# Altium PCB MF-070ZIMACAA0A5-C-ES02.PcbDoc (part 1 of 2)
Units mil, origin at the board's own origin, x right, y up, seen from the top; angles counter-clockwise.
Board outline 4023.75 x 4574.93 mil, 4 copper layers (TopLayer, LAYER2:GND, LAYER3:PW, BottomLayer); 140 components, 66 nets, 413 pads, 523 vias.
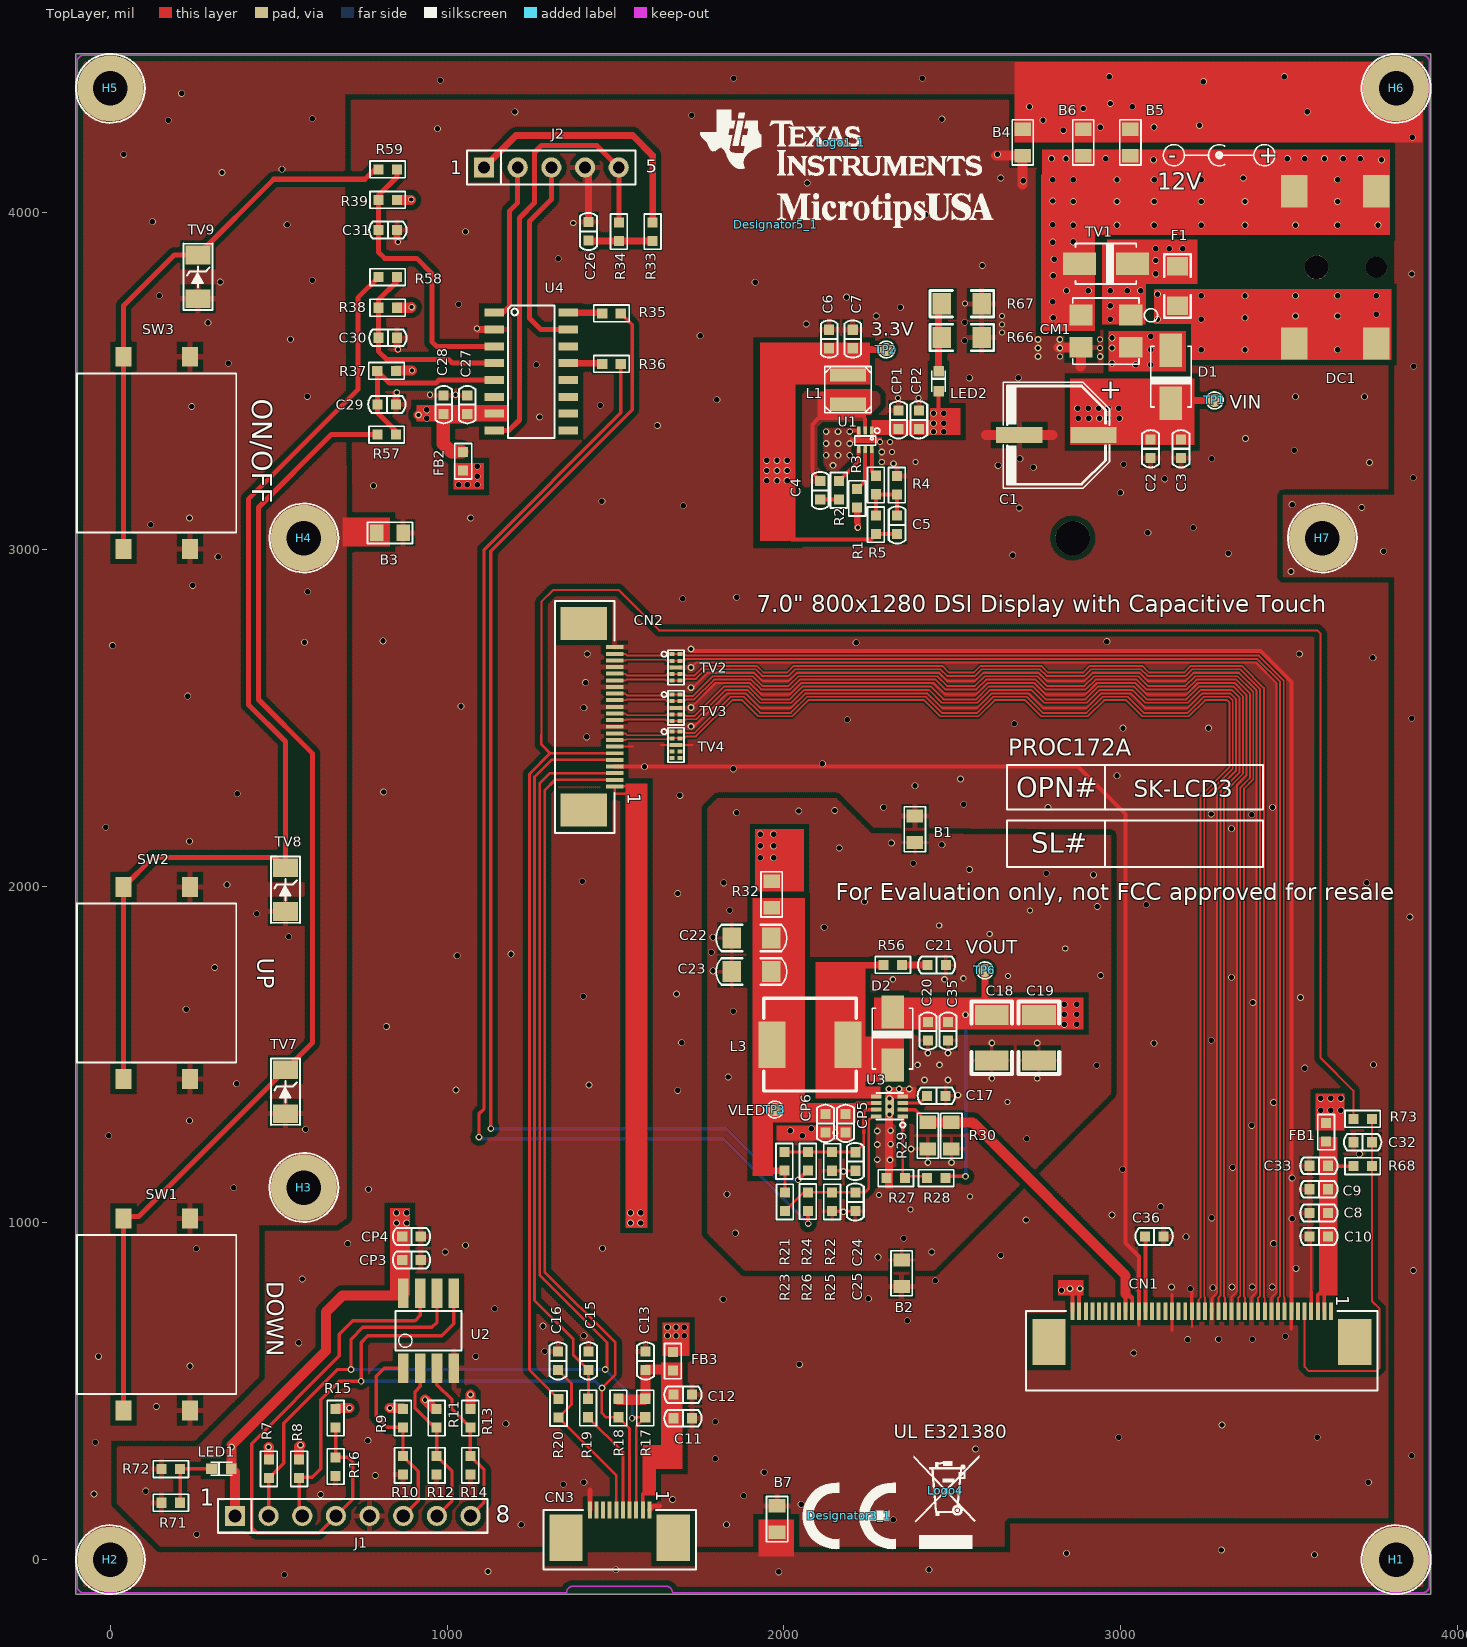
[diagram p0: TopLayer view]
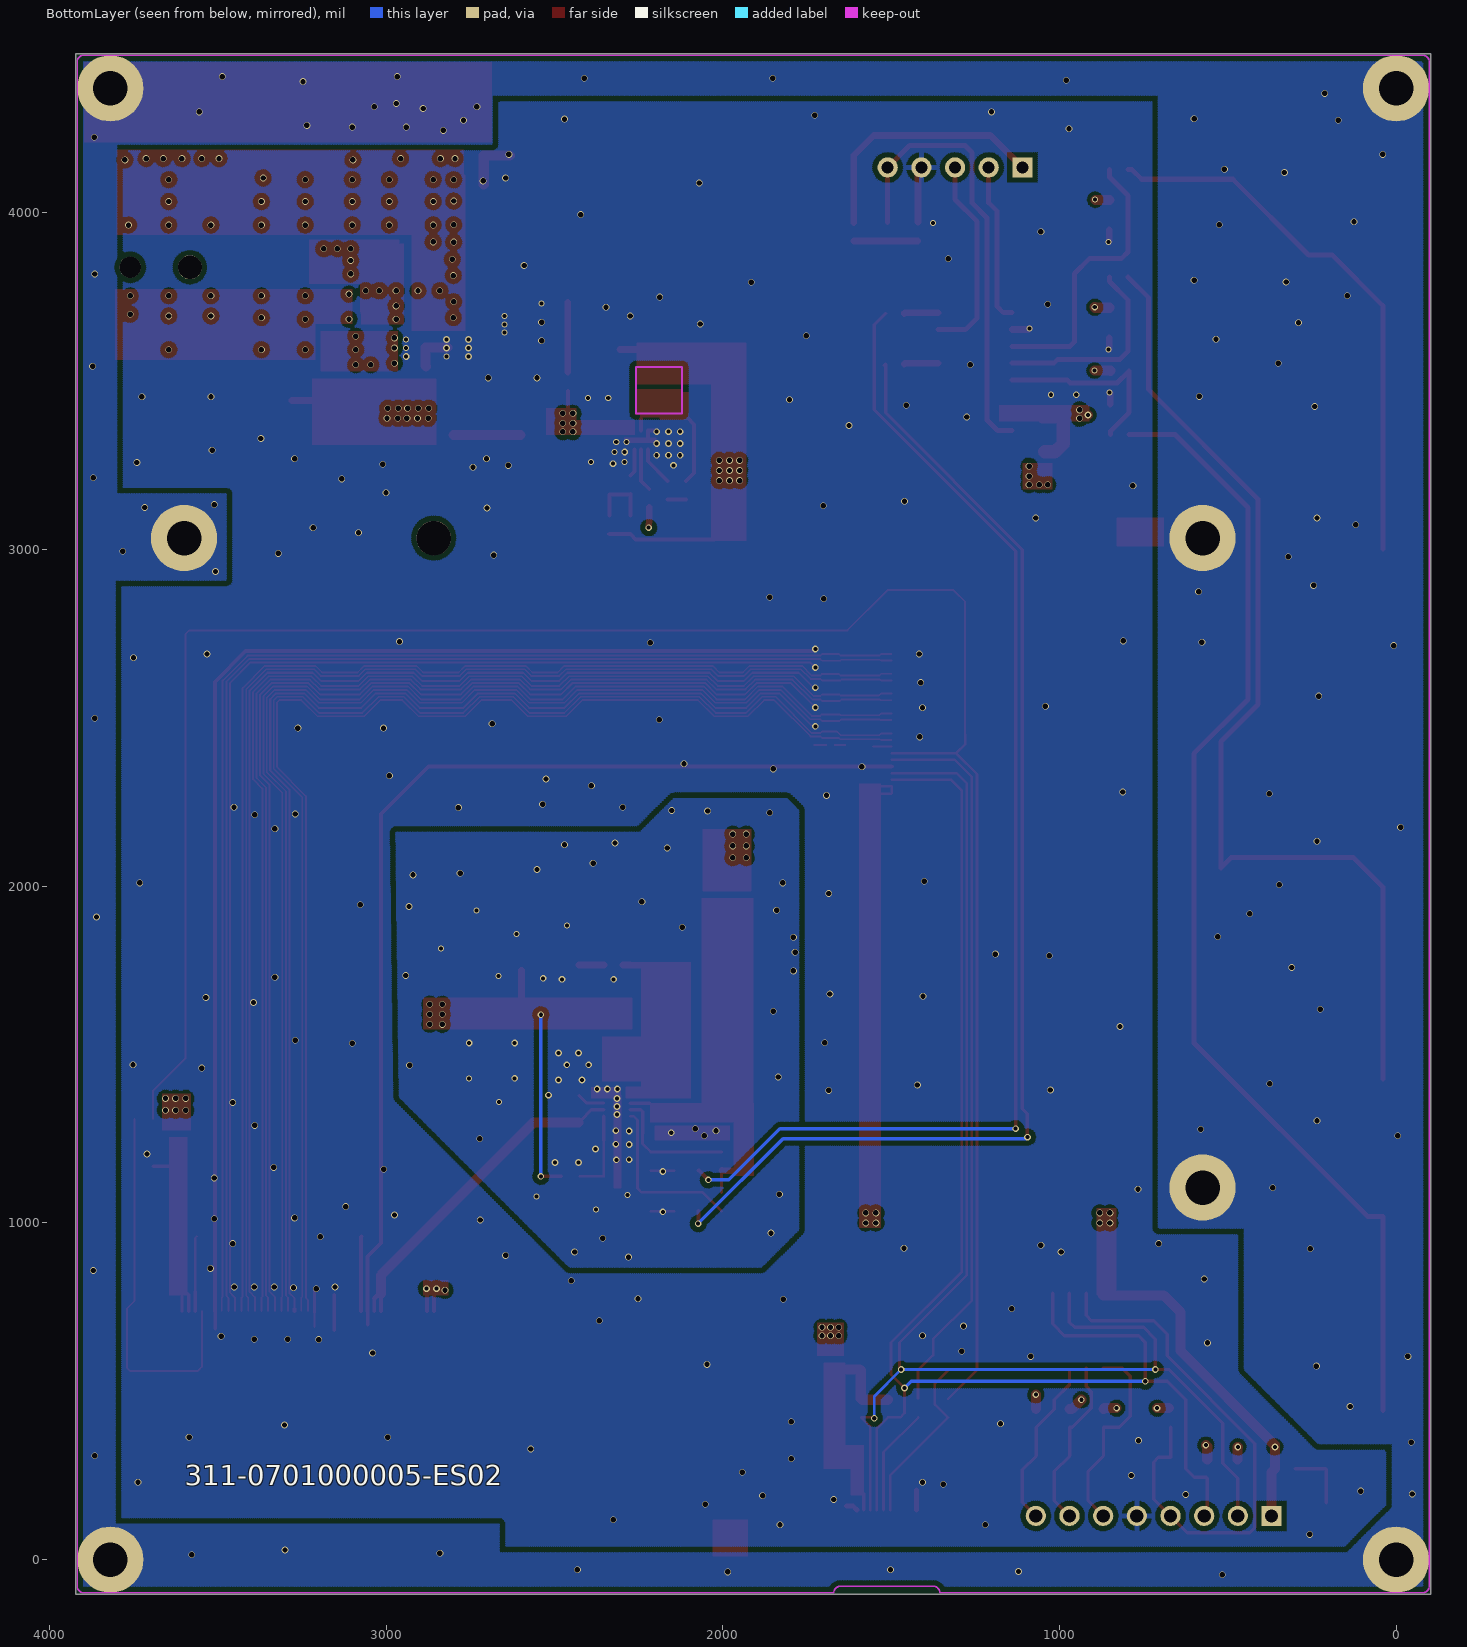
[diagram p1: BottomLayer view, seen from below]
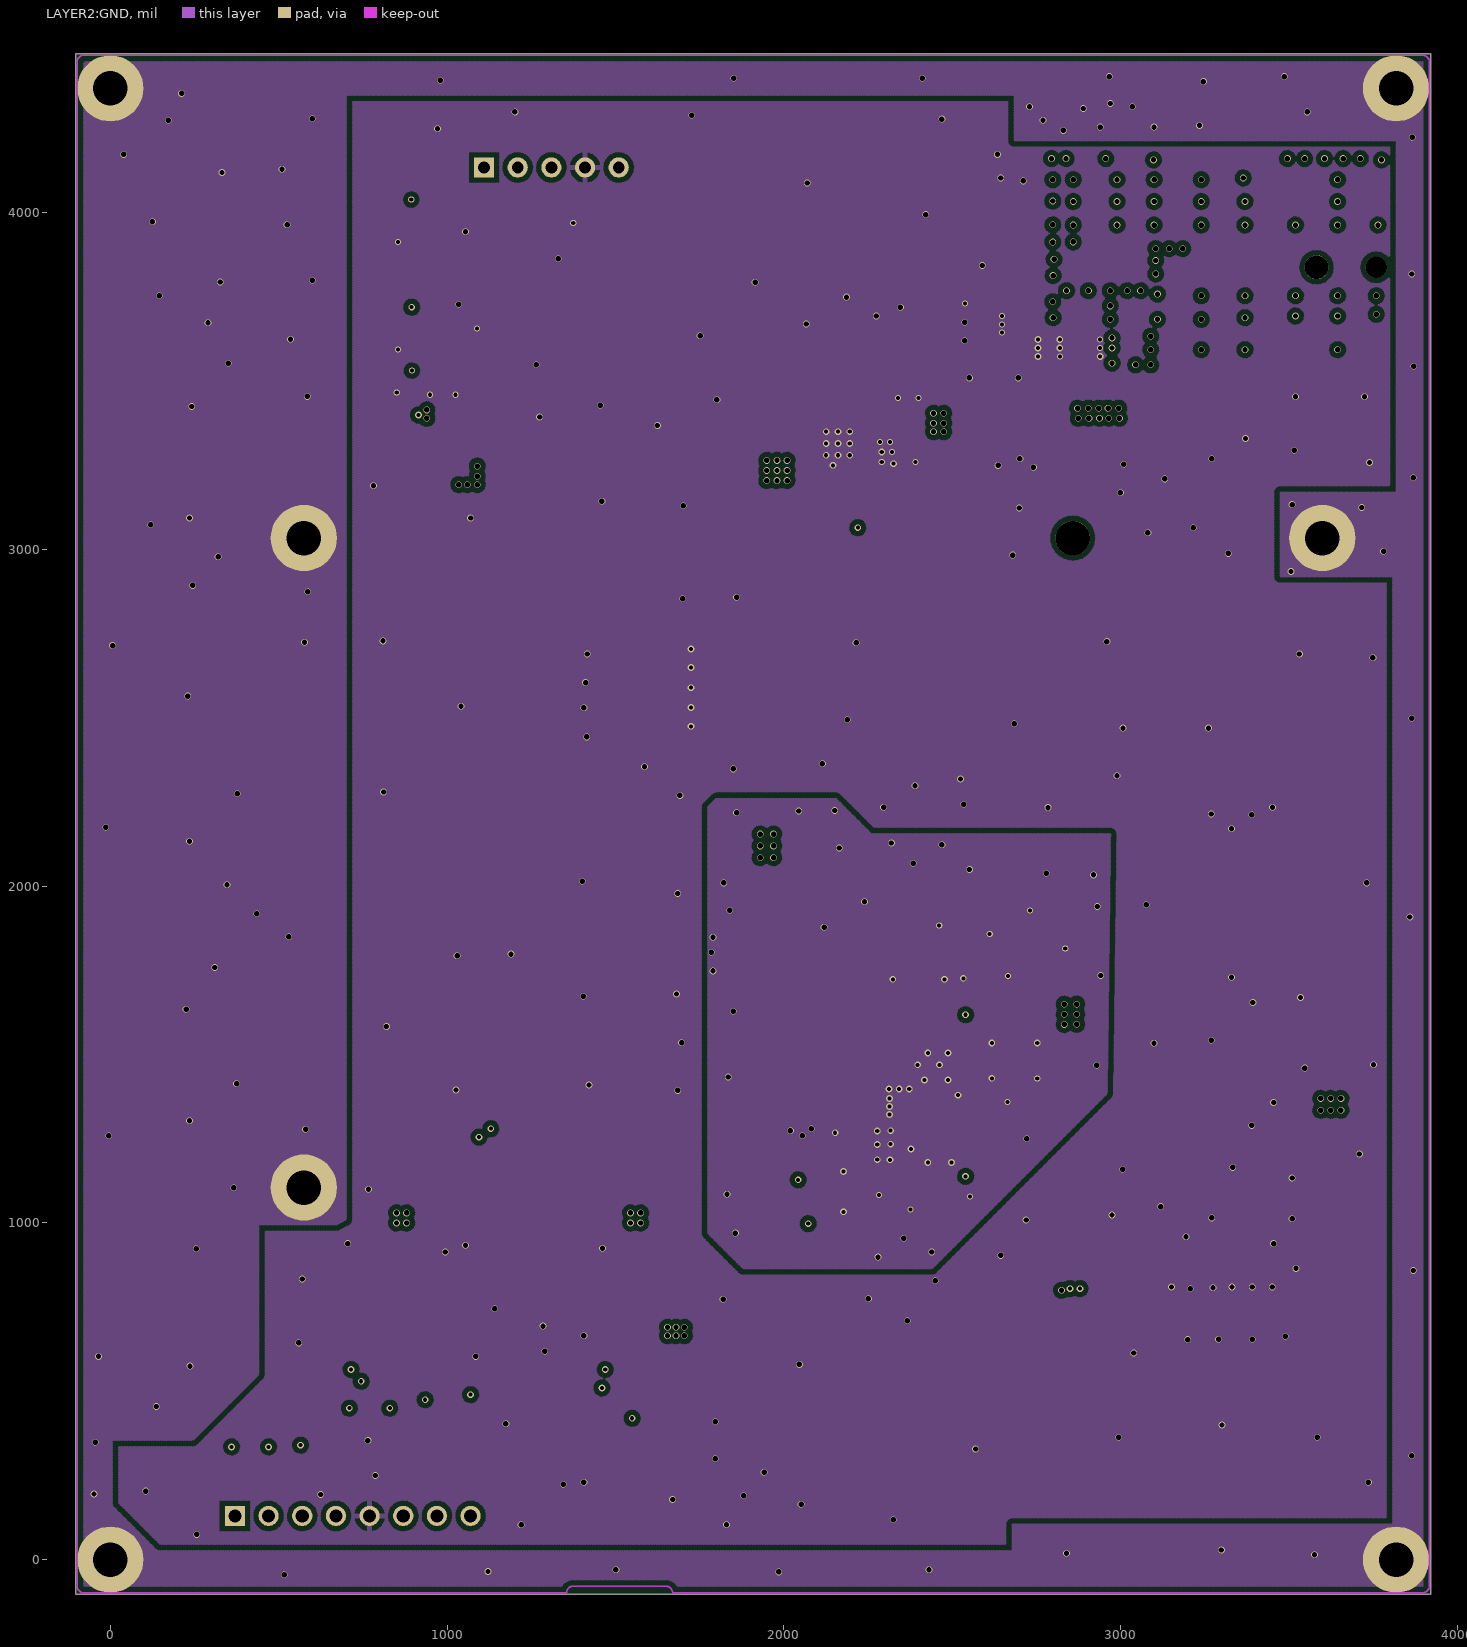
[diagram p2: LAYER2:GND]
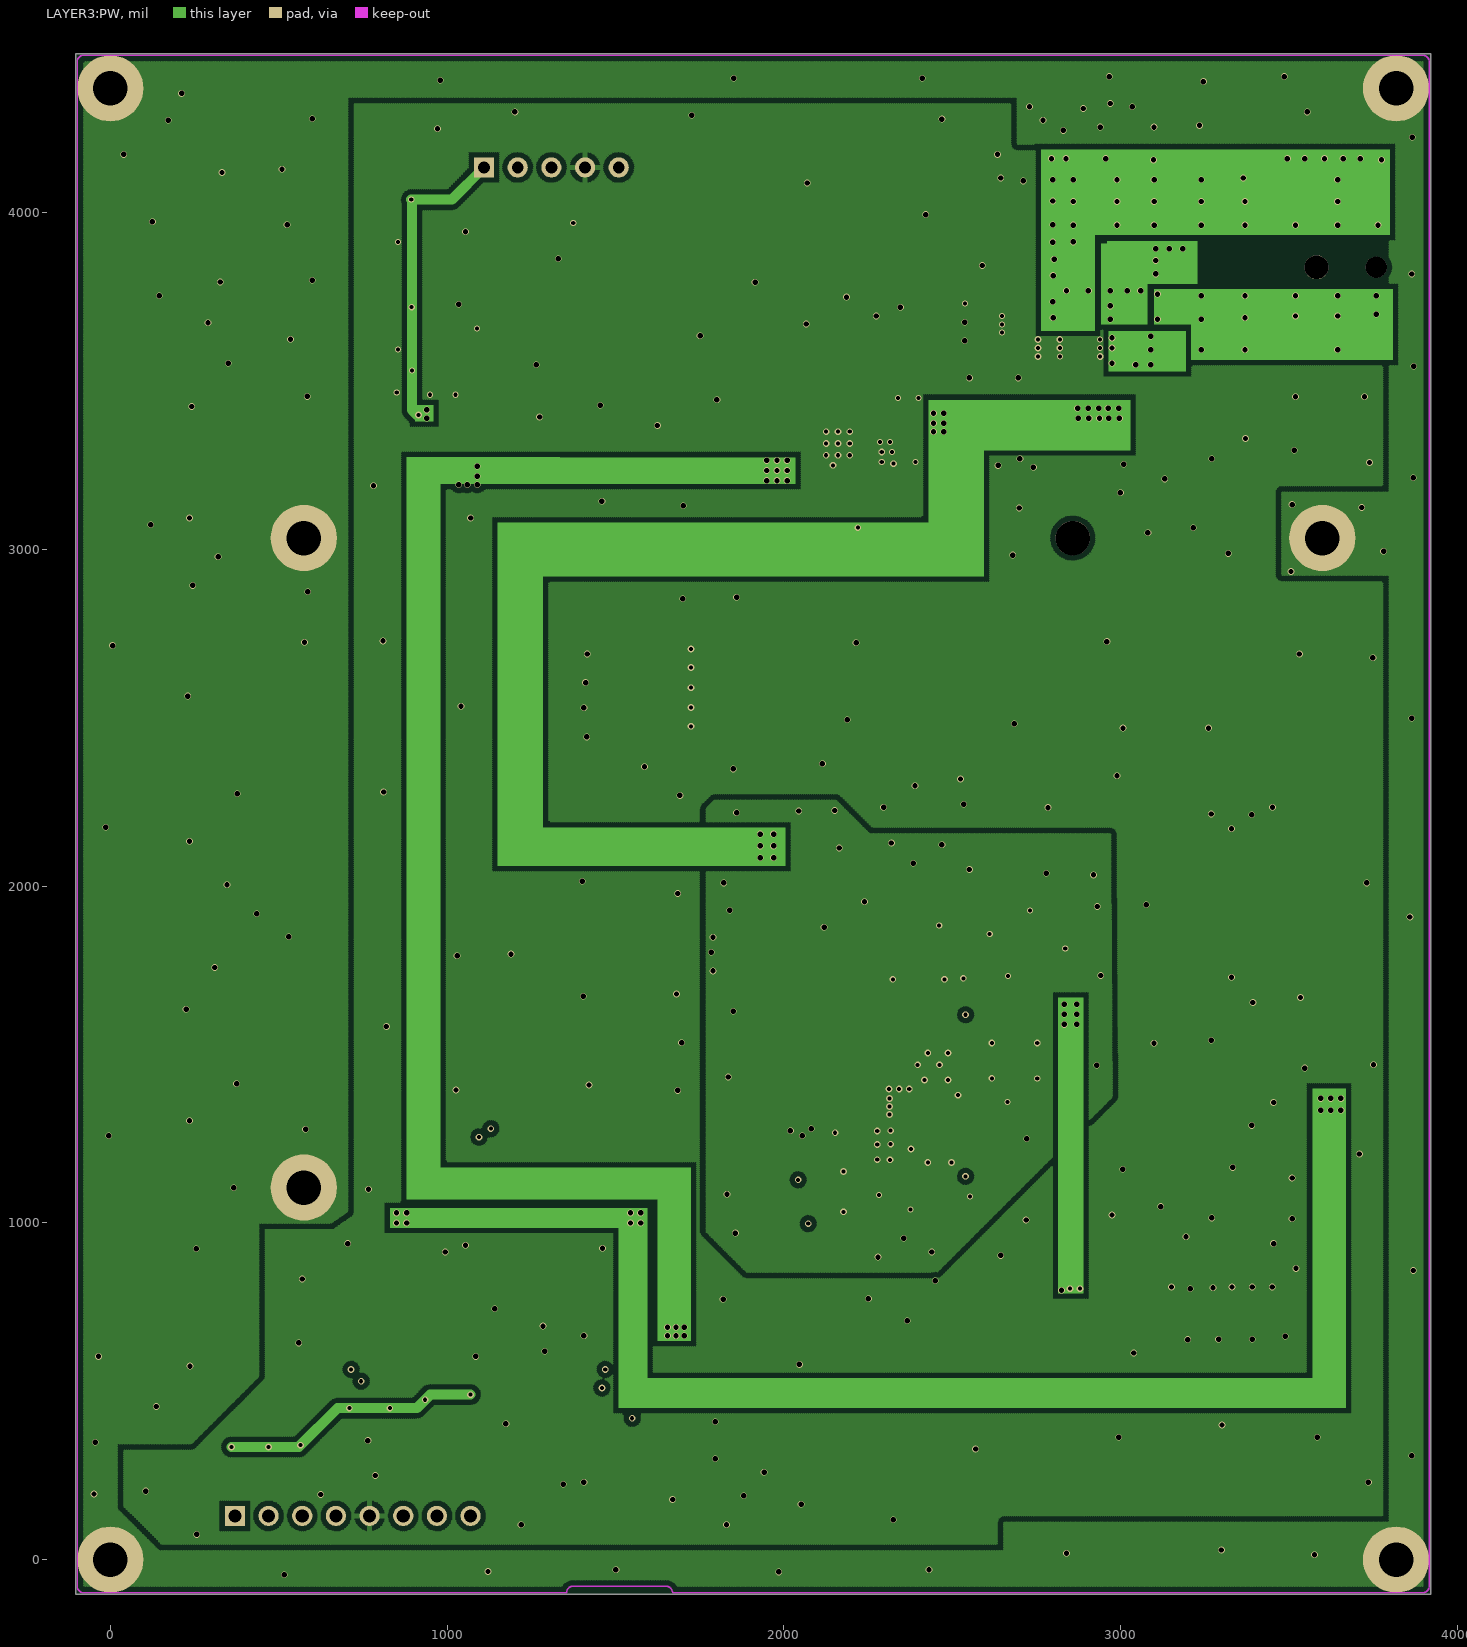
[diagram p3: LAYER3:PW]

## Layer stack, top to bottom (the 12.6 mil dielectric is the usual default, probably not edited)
TopSolder: solder mask 0.4, Solder Resist, Dk 3.5
TopLayer: signal copper 1.4
Dielectric1: core 12.6, FR-4, Dk 4.8
LAYER2:GND: signal copper 1.4
Dielectric2: prepreg 12.6, FR-4, Dk 4.8
LAYER3:PW: signal copper 1.4
Dielectric3: core 12.6, FR-4, Dk 4.8
BottomLayer: signal copper 1.4
BottomSolder: solder mask 0.4, Solder Resist, Dk 3.5

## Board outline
-102.43,-102.43 3921.32,-102.43 3921.32,4472.5 -102.43,4472.5

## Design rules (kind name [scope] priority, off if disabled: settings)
Clearance Clearance_3 [(InPoly) vs InNetClass('PN')] p1: gap=5.25 ignorepadtopadclearanceinfootprint=FALSE
Clearance Clearance_1 [InNetClass('PN')] p2: gap=4.5 ignorepadtopadclearanceinfootprint=FALSE
Clearance Clearance_2 [(InPoly)] p3: gap=15 ignorepadtopadclearanceinfootprint=FALSE
Clearance [All] p4: gap=6 ignorepadtopadclearanceinfootprint=FALSE
FabricationTestPointUsage TestPointUsage [All] p1: valid=0 allowmultiple=FALSE
FabricationTestpoint Testpoint [All] p1: side=3 testpointundercomponent=TRUE minsize=40 maxsize=100 preferedsize=60 minholesize=20 maxholesize=40 preferedholesize=32 testpointgrid=1 allowsidetop=TRUE allowsidebottom=TRUE usegrid=TRUE gridtolerance=0.01
PlaneConnect PlaneConnect_5 [All] p1: planeconnectstyle=Relief reliefexpansion=20 reliefentries=4 reliefconductorwidth=10 reliefairgap=10
PolygonConnect PolygonConnect_1 [HasFootprint('PAD5(2.6)')] p1: connectstyle=Direct reliefconductorwidth=10 reliefentries=4 polygonreliefangle="90 Angle" airgapwidth=10
PolygonConnect [All] p2: connectstyle=Relief reliefconductorwidth=15 reliefentries=4 polygonreliefangle="90 Angle" airgapwidth=10
RoutingLayers [All] p1: top layer_v5=TRUE mid layer 1_v5=FALSE mid layer 2_v5=FALSE bottom layer_v5=TRUE
RoutingVias [All] p1: holewidth=12 width=20 viastyle="Through Hole" minholewidth=12 minwidth=20 maxholewidth=12 maxwidth=20
SolderMaskExpansion SolderMaskExpansion_1 [(IsVia)] p1: expansion=-20 istentingtop=FALSE
SolderMaskExpansion [All] p2: expansion=4 istentingtop=FALSE
Width Width_1 [InNetClass('PN')] p1: maxlimit=5.5 minlimit=5.5 preferedwidth=5.5
Width [All] p2: maxlimit=200 minlimit=4 preferedwidth=8
26 further rules are at their usual default settings.

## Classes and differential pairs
net class PN: MIPI_0N MIPI_0P MIPI_1N MIPI_1P MIPI_2N MIPI_2P MIPI_3N MIPI_3P MIPI_CLKN MIPI_CLKP

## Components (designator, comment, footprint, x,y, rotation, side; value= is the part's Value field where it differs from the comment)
B1 "0 OHM" SR0805-A#1 2390,2170 r270 top
B2 "0 OHM" SR0805-A#1 2350,850 r90 top
B3 "OPEN" SR0805-A#1 830,3050 r0 top
B4 "OPEN" SR0805-A#1 2710,4210 r270 top
B5 "4.99 1% OHM" SR0805-A#1 3030,4210 r270 top
B6 "4.99 1% OHM" SR0805-A#1 2890,4210 r270 top
B7 "OPEN" SR0805-A#1 1980,120 r90 top
C1 "47uF/35V,GMV047M" PCAP3L-1 2810,3340 r90 top
C2 "0.1u/50V X7R" SC0603-A#1 3090,3300 r270 top
C3 "10uF /25V X5R" SC0603-A#1 3180,3300 r270 top
C4 "1uF/25V X7R" SC0603-A#2 2108.31,3176.07 r270 top
C5 "15pF/50V NP0" SC0603-A#2 2336.66,3073.7 r270 top
C6 "22uF/10V X5R" SC0603-A#1 2135,3625 r90 top
C7 "22uF/10V X5R" SC0603-A#1 2205,3625 r90 top
C8 "0.1u/50V X7R" SC0603-A#1 3590,1030 r180 top
C9 "1uF/25V X5R" SC0603-A#1 3590,1100 r180 top
C10 "0.01u/50V X7R" SC0603-A#1 3590,960 r180 top
C11 "0.1u/50V X7R" SC0603-A#3 1700,420 r0 top
C12 "0.1u/50V X7R" SC0603-A#3 1700,490 r0 top
C13 "10uF/25V X5R" SC0603-A#3 1590,590 r90 top
C15 "OPEN" SC0603-A#3 1420,590 r90 top
C16 "OPEN" SC0603-A#3 1330,590 r90 top
C17 "1uF /25V X7R" SC0603-A#4 2453.38,1377.62 r180 top
C18 "10u/50V X5R" SC1210-A 2618.07,1549.76 r90 top
C19 "10u/50V X5R" SC1210-A 2758.07,1549.76 r90 top
C20 "0.1u/50V X7R" SC0603-A#4 2428.07,1569.76 r90 top
C21 "OPEN" SC0603-A#4 2454,1766.09 r0 top
C22 "10u/25V X7R" SC1206-A 1904.13,1846.46 r0 top
C23 "10u/25V X7R" SC1206-A 1904.13,1746.46 r0 top
C24 "OPEN" SC0603-A#1 2212.9,1183.07 r270 top
C25 "OPEN" SC0603-A#1 2212.9,1063.07 r270 top
C26 "0.1u/50V X7R" SC0603-A#1 1419.91,3944.65 r90 top
C27 "0.1u/50V X7R" SC0603-A#1 1060,3430 r90 top
C28 "10uF /25V X5R" SC0603-A#1 990,3430 r90 top
C29 "1uF /25V X7R" SC0603-A#1 820.71,3431.57 r0 top
C30 "1uF /25V X7R" SC0603-A#1 823.82,3629.29 r0 top
C31 "1uF /25V X7R" SC0603-A#1 823.82,3949.29 r0 top
C32 "0.1u/50V X7R" SC0603-A#5 3720,1240 r180 top
C33 "10u/25V X5R" SC0603-A#5 3590,1170 r180 top
C35 "0.1u/50V X7R" SC0603-A#4 2488.07,1569.76 r90 top
C36 "1u/25V X7R" SC0603-A#5 3100,960 r0 top
CM1 "PSRF0540TL-102-2" GDLW0504P 2956.77,3648.69 r270 top
CN1 "FPCB 60PIN" CN1 3625.71,738.19 r270 top locked
CN2 "FPCB 22 PIN" CN2-22 1498.03,2296.74 r270 top locked
CN3 "PCT" CN3-10 1601.3,147.64 r270 top locked
CP1 "10uF/25V X5R" SC0603-A#2 2341.23,3385.21 r90 top
CP2 "0.1u/50V X7R" SC0603-A#1 2401.23,3385.21 r90 top
CP3 "0.1u/50V X7R" SC0603-A#1 895,890 r180 top
CP4 "10uF/25V X5R" SC0603-A#1 895,960 r180 top
CP5 "0.1u/50V X7R" SC0603-A#4 2184,1296.09 r270 top
CP6 "10uF /25V X5R" SC0603-A#4 2124,1296.09 r270 top
D1 "SX34LF" SMA#1 3150.08,3513.86 r270 top
D2 "CDBA360LR-HF" SMA#2 2323.38,1547.62 r90 top
DC1 "DC00500-AH9 TO A" DC 3759.84,4064.96 r0 top
Designator3_1 "Comment" CE_Mark_5mm 2195,130 r0 top
Designator5_1 "Comment" MICROTIPS 1976.67,3965 r0 top
F1 "CQ12LH002" SR1206-A#1 3170.08,3783.86 r270 top
FB1 "PBDA0603M6012A" SR0603-A#1 3610,1270 r270 top
FB2 "PBDA0603M6012A" SR0603-A#1 1048.82,3262.22 r90 top
FB3 "PBDA0603M6012A" SR0603-A#1 1670,590 r270 top
H1 "CON1" PAD5(2.6) 3818.9,0 r270 top locked
H2 "CON1" PAD5(2.6) 0,0 r270 top locked
H3 "CON1" PAD5(2.6) 574.8,1105.27 r270 top locked
H4 "CON1" PAD5(2.6) 574.8,3034.4 r270 top locked
H5 "CON1" PAD5(2.6) 0,4370.08 r270 top locked
H6 "CON1" PAD5(2.6) 3818.9,4370.08 r270 top locked
H7 "CON1" PAD5(2.6) 3599.79,3034.4 r270 top locked
J1 "2.54mm/8pin" SIP\8P 370,130 r90 top
J2 "2.54mm/5pin" SIP\5P 1109.91,4134.65 r90 top
L1 "PSPNAQ3015-2R2" L-GNR3015P 2191.23,3475.21 r180 top
L3 "10uH" L3 2078.07,1529.76 r180 top
LED1 "LG-1928UG-CT" LED 330,270 r0 top
LED2 "LG-192HRF-CT" LED 2460,3500 r270 top
Logo1_1 "Texas Instruments" TI_Stacked_Overlay_Small 2170,4208.74 r0 top (schematic designator Logo1)
Logo4 "WEEE logo" WEEE_Minimum 2481.67,205 r0 top
R1 "100K 1%" SR0603-A#2 2218.55,3152.44 r90 top
R2 "30R 5%" SR0603-A#2 2163.43,3176.07 r270 top
R3 "47K 1%" SR0603-A#2 2273.67,3191.81 r270 top
R4 "13K 1%" SR0603-A#2 2336.66,3191.81 r90 top
R5 "40.2K 1%" SR0603-A#2 2273.67,3073.7 r270 top
R7 "4.7K 1%" SR0603-A#1 470,270 r270 top
R8 "4.7K 1%" SR0603-A#1 560,270 r270 top
R9 "OPEN" SR0603-A#1 870,420 r90 top
R10 "10K 1%" SR0603-A#1 870,280 r90 top
R11 "10K 1%" SR0603-A#1 970,420 r90 top
R12 "OPEN" SR0603-A#1 970,280 r90 top
R13 "OPEN" SR0603-A#1 1070,420 r90 top
R14 "10K 1%" SR0603-A#1 1070,280 r90 top
R15 "10K 1%" SR0603-A#1 670,420 r90 top
R16 "OPEN" SR0603-A#1 670,276.26 r90 top
R17 "OPEN" SR0603-A#3 1590,450 r90 top
R18 "OPEN" SR0603-A#3 1510,450 r90 top
R19 "0 OHM" SR0603-A#3 1420,450 r90 top
R20 "0 OHM" SR0603-A#3 1330,450 r270 top
R21 "OPEN" SR0603-A#1 2002.9,1183.07 r90 top
R22 "100K 1%" SR0603-A#1 2142.9,1183.07 r270 top
R23 "OPEN" SR0603-A#1 2002.9,1063.07 r270 top
R24 "22 OHM 1%" SR0603-A#1 2072.9,1183.07 r90 top
R25 "100K 1%" SR0603-A#1 2142.9,1063.07 r270 top
R26 "22 OHM 1%" SR0603-A#1 2072.9,1063.07 r90 top
R27 "48.7K 1%" SR0603-A#4 2332.9,1133.07 r0 top
R28 "1M 1%" SR0603-A#4 2452.9,1133.07 r0 top
R29 "3.3 OHM 1%" SR0805-A#2 2428.07,1259.76 r90 top
R30 "3.3 OHM 1%" SR0805-A#2 2498.07,1259.76 r90 top
R32 "0 OHM" SR0805-A#1 1964.13,1976.46 r270 top
R33 "100K 1%" SR0603-A#1 1609.91,3944.65 r270 top
R34 "1K 1%" SR0603-A#1 1509.91,3944.65 r270 top
R35 "0 OHM" SR0603-A#1 1488.82,3702.22 r180 top
R36 "0 OHM" SR0603-A#1 1488.82,3552.22 r180 top
R37 "100K 1%" SR0603-A#1 820.71,3531.57 r180 top
R38 "100K 1%" SR0603-A#1 823.82,3719.29 r180 top
R39 "100K 1%" SR0603-A#1 823.82,4039.29 r180 top
R56 "OPEN" SR0603-A#4 2324,1766.09 r0 top
R57 "1K 1%" R0603 820.71,3341.57 r180 top
R58 "1K 1%" R0603 823.82,3809.29 r180 top
R59 "1K 1%" R0603 823.82,4129.29 r180 top
R66 "2.4K 1%" SR1206-A#2 2528.07,3630.35 r0 top
R67 "2.4K 1%" SR1206-A#2 2528.07,3730.35 r0 top
R68 "10K 1%" SR0603-A#5 3720,1170 r180 top
R71 "OPEN" SR0603-A#5 180,170 r180 top
R72 "220 OHM 1%" SR0603-A#5 180,270 r180 top
R73 "OPEN" SR0603-A#5 3720,1310 r180 top
SW1 "TS12H4.3" SW 137.8,728.35 r0 top locked
SW2 "TS12H4.3" SW 137.8,1712.6 r0 top locked
SW3 "TS12H4.3" SW 137.8,3287.4 r0 top locked
TP1 "VIN" PAD0.8MM#1 3280.08,3443.86 r0 top
TP2 "3.3V" PAD0.8MM#1 2305,3595 r0 top
TP3 "VLED" PAD0.8MM#2 1974.13,1336.46 r180 top
TP6 "VOUT" PAD0.8MM#3 2598.07,1749.76 r180 top
TV1 "TV04A150J-HF" SMA#1 2956.77,3848.69 r0 top
TV2 "CPDA10R5V0U-HF" SGP2510P8 1680,2650 r270 top
TV3 "CPDA10R5V0U-HF" SGP2510P8 1680,2530 r270 top
TV4 "CPDA10R5V0U-HF" SGP2510P8 1680,2420 r270 top
TV7 "P4FL3.3A" SOD-123L 520,1390 r270 top
TV8 "P4FL3.3A" SOD-123L 520,1990 r270 top
TV9 "P4FL3.3A" SOD-123L 260,3810 r270 top
U1 "MP1653" SOT-563 2242.17,3325.67 r180 top
U2 "24LC02" SOP8 945,680 r0 top
U3 "RT8511BGQW" QFN2X2 2314,1346.09 r90 top
U4 "HT66F30-1" NSOP-16P 1250.1,3528.6 r270 top

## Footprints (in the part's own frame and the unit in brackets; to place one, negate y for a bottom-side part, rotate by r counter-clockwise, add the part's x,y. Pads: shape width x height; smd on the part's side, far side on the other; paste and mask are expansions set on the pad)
CE_Mark_5mm [mil] "Minimum text height for CE Mark"
  silkscreen extent -138,-99 138,99
CN1 [mm]
  rect 1.3x0.3 smd: 1(0,0) 2(0,-0.5) 3(0,-1) 4(0,-1.5) 5(0,-2) 6(0,-2.5) 7(0,-3) 8(0,-3.5) 9(0,-4) 10(0,-4.5) 11(0,-5) 12(0,-5.5) 13(0,-6) 14(0,-6.5) 15(0,-7) 16(0,-7.5) 17(0,-8) 18(0,-8.5) 19(0,-9) 20(0,-9.5) 21(0,-10) 22(0,-10.5) 23(0,-11) 24(0,-11.5) 25(0,-12) 26(0,-12.5) 27(0,-13) 28(0,-13.5) 29(0,-14) 30(0,-14.5) 31(0,-15) 32(0,-15.5) 33(0,-16) 34(0,-16.5) 35(0,-17) 36(0,-17.5) 37(0,-18) 38(0,-18.5) 39(0,-19) 40(0,-19.5)
  rect 3.5x2.5 smd: G(2.325,1.79) G(2.325,-21.29)
  silkscreen extent 0,-23 6,3.5
CN2-22 [mm]
  rect 0.3x1.3 smd: 1(0,0) 2(-0.5,0) 3(-1,0) 4(-1.5,0) 5(-2,0) 6(-2.5,0) 7(-3,0) 8(-3.5,0) 9(-4,0) 10(-4.5,0) 11(-5,0) 12(-5.5,0) 13(-6,0) 14(-6.5,0) 15(-7,0) 16(-7.5,0) 17(-8,0) 18(-8.5,0) 19(-9,0) 20(-9.5,0) 21(-10,0) 22(-10.5,0)
  rect 2.5x3.5 smd: G(-12.29,-2.325) G(1.79,-2.325)
  silkscreen extent -14,-4.5 3.5,0
CN3-10 [mm]
  rect 1.3x0.3 smd: 1(0,0) 2(0,-0.5) 3(0,-1) 4(0,-1.5) 5(0,-2) 6(0,-2.5) 7(0,-3) 8(0,-3.5) 9(0,-4) 10(0,-4.5)
  rect 3.5x2.5 smd: G(2.1,1.79) G(2.1,-6.29)
  silkscreen extent 0,-8 4.5,3.5
DC [mm]
  rect 2x2.45 smd: 3(0,0) 4(-6.2,0) 5(-6.2,-11.5) 5(0,-11.5)
  round 1.8 hole 1.8 unplated: NC(-4.5,-5.75)
  round 1.6 hole 1.6 unplated: NC(0,-5.75)
GDLW0504P [mm]
  rect 1.55x1.75 smd: 1(-1.223,1.88) 2(1.217,1.88) 3(1.217,-1.87) 4(-1.223,-1.87)
  silkscreen extent -2.5,-2.5 2.5,3.9
L3 [mm]
  rect 2.05x3.5 smd: 1(-2.875,0) 2(2.875,0)
  silkscreen extent -3.5,-3.5 3.5,3.5
L-GNR3015P [mm]
  rect 2.7x1 smd: 1(0,1.105) 2(0,-1.095)
  BottomLayer keep-out lines w0.152: 1.8,1.8 -1.7,1.8 -1.7,-1.7 1.8,-1.7 1.8,1.8
  silkscreen extent -1.75,-1.75 1.75,1.75
LED [mm]
  rect 0.8x0.8 smd: 1(0.75,0) 2(-0.75,0)
  silkscreen extent -0.8,-0.5 0.8,0.5
MICROTIPS [mil]
  silkscreen extent 5,-9 645,93
NSOP-16P [mm]
  rect 0.6x1.5 smd: 1(-4.445,-2.79) 2(-3.175,-2.79) 3(-1.905,-2.79) 4(-0.635,-2.79) 5(0.635,-2.79) 6(1.905,-2.79) 7(3.175,-2.79) 8(4.445,-2.79) 9(4.445,2.79) 10(3.175,2.79) 11(1.905,2.79) 12(0.635,2.79) 13(-0.635,2.79) 14(-1.905,2.79) 15(-3.175,2.79) 16(-4.445,2.79)
  silkscreen extent -5,-1.75 5,1.75
PAD0.8MM#1 [mm]
  round 1 smd: 1(-0.002,-0.018)
  silkscreen extent -0.64,-0.65 0.63,0.62
PAD0.8MM#2 [mm]
  round 1 smd: 1(0,-0.011)
  silkscreen extent -0.64,-0.65 0.63,0.62
PAD0.8MM#3 [mm]
  round 1 smd: 1(0.006,-0.013)
  silkscreen extent -0.63,-0.65 0.64,0.62
PAD5(2.6) [mm]
  round 5 hole 2.6: 1(0,0)
  silkscreen extent -2.6,-2.6 2.6,2.6
PCAP3L-1 [mm]
  rect 1.2x3.5 smd: 1(0,-2.8) 2(0,2.8)
  silkscreen extent -4,-4 4,4
QFN2X2 [mm]
  rect 0.3x0.8 smd: 1(-0.741,-1.011) 2(-0.241,-1.011) 3(0.259,-1.011) 4(0.759,-1.011) 5(0.759,0.989) 6(0.259,0.989) 7(-0.241,0.989) 8(-0.741,0.989)
  rect 1.25x0.65 smd: 9(0.009,-0.011)
  silkscreen extent -1.6,-1.2 1.01,0.99
R0603 [mil]
  rect 30x30 smd: 1(-27.5,0) 2(27.5,0)
  silkscreen extent -52,-25 53,25
SC0603-A#1 [mil]
  rect 30x30 smd: 1(-27.05,-0.12) 2(27.95,-0.12)
  silkscreen extent -55,-25 56,25
SC0603-A#2 [mil]
  rect 30x30 smd: 1(-27.2,0.34) 2(27.8,0.34)
  silkscreen extent -55,-25 56,25
SC0603-A#3 [mil]
  rect 30x30 smd: 1(-26.98,0.03) 2(28.02,0.03)
  silkscreen extent -55,-25 56,25
SC0603-A#4 [mil]
  rect 30x30 smd: 1(-27.4,-0.13) 2(27.6,-0.13)
  silkscreen extent -55,-25 55,25
SC0603-A#5 [mil]
  rect 30x30 smd: 1(-27.06,0.07) 2(27.94,0.07)
  silkscreen extent -55,-25 56,25
SC1206-A [mm]
  rect 1.4x1.6 smd: 1(-1.488,0.002) 2(1.512,0.002)
  silkscreen extent -2.66,-1 2.66,1
SC1210-A [mil]
  rect 60x100 smd: 1(-67.13,-0.14) 2(67.87,-0.14)
  silkscreen extent -107,-60 108,60
SGP2510P8 [mm]
  rect 0.3x0.38 smd: 1(-1,-0.305) 2(-0.5,-0.305) 3(0,-0.305) 3(0,0.005) 4(0.5,-0.305) 5(1,-0.305) 6(1,0.315) 7(0.5,0.315) 8(0,0.315) 9(-0.5,0.315) 10(-1,0.315)
  silkscreen extent -1.3,-1.09 1.3,0.61
SIP\5P [mil]
  rect 60x60 hole 35.43: 1(0.35,-0.09)
  round 60 hole 35.43: 2(0.35,-100.09) 3(0.35,-200.09) 4(0.35,-300.09) 5(0.35,-400.09)
  silkscreen extent -50,-450 50,50
SIP\8P [mil]
  rect 60x60 hole 39.37: 1(0,0)
  round 60 hole 39.37: 2(0,-100) 3(0,-200) 4(0,-300) 5(0,-400) 6(0,-500) 7(0,-600) 8(0,-700)
  silkscreen extent -50,-750 50,50
SMA#1 [mm]
  rect 2.5x1.7 smd: 1(-1.993,0.004) 2(2.007,0.004)
  silkscreen extent -2.29,-1.52 2.29,1.55
SMA#2 [mm]
  rect 2.5x1.7 smd: 1(-2,0) 2(2,0)
  silkscreen extent -2.29,-1.52 2.28,1.55
SOD-123L [mm]
  rect 1.4x1.9 smd: 1(-1.651,0.003) 2(1.649,0.003)
  silkscreen extent -2.5,-1.1 2.5,1.1
SOP8 [mm]
  rect 0.8x2.2 smd: 1(-1.897,-2.825) 2(-0.627,-2.825) 3(0.643,-2.825) 4(1.913,-2.825) 5(1.913,2.825) 6(0.643,2.825) 7(-0.627,2.825) 8(-1.897,2.825)
  silkscreen extent -2.49,-1.5 2.51,1.5
SOT-563 [mm]
  rect 0.25x0.6 smd: 1(-0.5,-0.7) 2(0,-0.7) 3(0.5,-0.7) 4(0.5,0.7) 5(0,0.7) 6(-0.5,0.7)
  silkscreen extent -1.1,-0.9 0.8,0.4
SR0603-A#1 [mil]
  rect 30x30 smd: 1(-27.22,0.81) 2(27.78,0.81)
  silkscreen extent -52,-24 53,26
SR0603-A#2 [mil]
  rect 30x30 smd: 1(-27.7,0.34) 2(27.3,0.34)
  silkscreen extent -53,-25 52,25
SR0603-A#3 [mil]
  rect 30x30 smd: 1(-27.09,1.13) 2(27.91,1.13)
  silkscreen extent -52,-24 53,26
SR0603-A#4 [mil]
  rect 30x30 smd: 1(-27.4,0.37) 2(27.6,0.37)
  silkscreen extent -52,-25 53,25
SR0603-A#5 [mil]
  rect 30x30 smd: 1(-27.24,1) 2(27.76,1)
  silkscreen extent -52,-24 53,26
SR0805-A#1 [mm]
  rect 1x1.25 smd: 1(-0.987,-0.004) 2(1.013,-0.004)
  silkscreen extent -1.69,-0.8 1.71,0.8
SR0805-A#2 [mm]
  rect 1x1.25 smd: 1(-1.007,-0.005) 2(0.993,-0.005)
  silkscreen extent -1.71,-0.8 1.69,0.8
SR1206-A#1 [mm]
  rect 1.4x1.6 smd: 1(-1.475,-0.014) 2(1.514,-0.014)
  silkscreen extent -2.37,-1.01 2.43,0.99
SR1206-A#2 [mm]
  rect 1.4x1.6 smd: 1(-1.475,-0.009) 2(1.514,-0.009)
  silkscreen extent -2.38,-1.01 2.42,0.99
SW [mm]
  rect 1.2x1.5 smd: A(-2.5,7.25) B(-2.5,-7.25) C(2.5,7.25) D(2.5,-7.25)
  silkscreen extent -6,-6 6,6
TI_Stacked_Overlay_Small [mil]
  silkscreen extent -418,-98 418,98
WEEE_Minimum [mil] "WEEElie bin"
  silkscreen extent -95,-172 99,104

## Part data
Logo1_1: library part CMP-0074838-1, "Texas Instrument Corporate Signature"
Logo4: library part CMP-0074769-1

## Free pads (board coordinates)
  round 102.36 hole 102.36 unplated: NC(2858.45,3034.4)

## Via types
v1: diameter 20, hole 16, TopLayer to BottomLayer, 413 vias
v2: diameter 20, hole 12, TopLayer to BottomLayer, 77 vias
v3: diameter 18, hole 12, TopLayer to BottomLayer, 33 vias

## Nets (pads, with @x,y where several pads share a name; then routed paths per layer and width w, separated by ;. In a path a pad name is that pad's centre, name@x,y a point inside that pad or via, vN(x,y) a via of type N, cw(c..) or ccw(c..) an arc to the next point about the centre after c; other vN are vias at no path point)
3.3V: C5.2 C6.1 C7.1 FB2.1 FB3.1 L1.2 R5.2 TP2.1 | length 437.8
  TopLayer w12: 2025,3090 2025,3030 2258.6,3030 2274.5,3045.91 C5.2@2337,3045.91
  TopLayer w20: 2245.72,3594.28 TP2.1@2304.9,3594.28
  other v1: 1655,665 1680,665 1705,665 1655,690 1680,690 1705,690 1035,3192.93 1060,3192.93 1090,3192.93 1950,3205 1980,3205 2010,3205 1090,3217.93 1950,3235 1980,3235 2010,3235 1090,3247.93 1950,3265 1980,3265 2010,3265
/RESET: C32.1 CN1.5 R68.1 R73.1 | length 1146.2
  TopLayer w6: CN1.5@3546.97,738.19 3546.97,573.03 3560,560 3760,560 3770,570 3770,745 3747.24,767.76 R73.1@3747.24,1309
A0: J1.6 R9.1 R10.2 U2.1 | length 602.8
  TopLayer w10: J1.6@870,130 915,175 915,261.97 R10.2@869.19,307.78 R9.1@869.19,392.78 822.78,392.78 790,425.55 790,545 813.76,568.76 U2.1@870.31,568.76
A1: J1.7 R11.1 R12.2 U2.2 | length 513.4
  TopLayer w10: U2.2@920.31,568.76 920.31,514.69 905,499.39 905,450 962.22,392.78 R11.1@969.19,392.78 R12.2@969.19,307.78 1015,261.97 1015,175 J1.7@970,130
A2: J1.8 R13.1 R14.2 U2.3 | length 509.6
  TopLayer w10: U2.3@970,565 970,520 1015,475 1015,446.97 R13.1@1069.19,392.78 R14.2@1069.19,307.78 1110,266.97 1110,170 J1.8@1070,130
DIMC: C17.2 U3.3 | length 80.9
  TopLayer w10: U3.3@2353.8,1356.29 2404.32,1356.29 C17.2@2425.78,1377.75
EEPROM_3.3V: CN2.1 CP3.2 CP4.2 FB1.1 J1.1 LED1.1 R7.1 R8.1 R9.2 R11.2 R13.2 R15.2 U2.8 | length 2138.6
  TopLayer w8: 1558.26,2296.74 CN2.1@1498.03,2296.74 1498.03,2276.97 1500,2275 1560,2275
  TopLayer w30: J1.1@370,130 370,259.53 360,269.53 360,340 640,620 640,735 690,785 U2.8@870,785 ; v2(470,335) 470.81,334.19 R7.1@470.81,297.22 ; R8.1@560.81,297.22 560.81,335.81 v2(565,340) ; R15.2@675,450 v2(710,450) ; v2(830,450) 866.97,450 R9.2@869.19,447.78 ; v2(935,475) 962.22,447.78 R11.2@969.19,447.78 ; R13.2@1069.19,447.78 1070,448.59 v2(1070,490)
  LAYER3:PW w30: v2(360,335) 560,335 675,450 910,450 950,490 v2(1070,490)
  other v1: 850,1000 880,1000 1545,1000 1575,1000 850,1030 880,1030 1545,1030 1575,1030 3595,1335 3625,1335 3655,1335 3595,1370 3625,1370 3655,1370
ENB: R26.1 R36.1 | length 3596.9
  TopLayer w10: v2(1095,1255) 1095,1325 1110,1340 1110,3000 1516.04,3406.04 R36.1@1516.04,3551.41 R36.1@1520.23,3547.22
  TopLayer w12: v2@2072.09,998.88 R26.1@2072.09,1035.85
  BottomLayer w10: v2(1095,1255) 1100,1250 1820.97,1250 v2@2072.09,998.88
  other v2: 2072.9,998.07
ENB1: C25.1 R23.2 R25.1 R26.2 U3.8 | length 506.7
  TopLayer w8: R23.2@2003.71,1035.29 2059.27,1090.85 2240.68,1090.85 2253,1103.18 2253,1305.88 2264.05,1316.92 U3.8@2275.06,1316.92
FB: CN1.31 CN1.32 R29.2 R30.2 U3.2 | length 1043.6
  TopLayer w10: U3.2@2353.37,1336.25 2390.05,1336.25 R29.2@2422.04,1304.26 ; 3025,789.53 3035.16,779.37 CN1.31@3035.16,738.19
  TopLayer w12: CN1.32@3015.47,738.19 3015.47,789.53 3035.16,775
  TopLayer w30: R29.2@2428.27,1298.84 2561.16,1298.84 3015.47,844.53 3015.47,789.53
FGND: B3.1 B4.1 B5.1 B6.1 B7.1 H1.1 H2.1 H3.1 H4.1 H5.1 H6.1 H7.1 SW1.C SW1.D SW2.C SW2.D SW3.C SW3.D TV7.2 TV8.2 TV9.2
  other v1: 516.67,-45 1985,-36.26 1121.67,-35 1501.67,-30 2431.67,-30 3576.67,15 2840,18.74 3300,28.74 -48.33,195 3865,308.74 -45,348.74 136.67,455 236.67,575 -35,603.74 3870,858.74 255,923.74 366.67,1105 -5,1258.74 580,1278.74 235,1303.74 375,1413.74 225,1635 310,1758.74 530,1850 3860,1908.74 435,1918.74 346.67,2005 235,2133.74 -13.33,2175 376.67,2275 3865,2498.74 230,2565 6.67,2715 576.67,2725 586.67,2875 245,2893.74 3506.67,2935 320,2978.74 3781.67,2995 120,3073.74 235,3093.74 3716.67,3125 3510,3133.74 3870,3213.74 241.67,3425 585,3455 3871.67,3545 350,3553.74 535,3625 290,3673.74 145,3753.74 326.67,3795 600,3800 3865,3818.74 525,3965 125,3973.74 331.67,4120 510,4130 40,4173.74 3866.67,4225 2830,4245 2940,4255 3100,4255 3235,4260 171.67,4275 2770,4275 600,4280 3555,4300 2890,4310 2730,4315 3035,4315 2970,4325 211.67,4355 3246.67,4390 980,4393.74 1851.67,4400 2411.67,4400 2966.67,4405 3486.67,4405
GND: B1.1 B2.1 B3.2 B4.2 B7.2 C1.2 C2.2 C3.2 C6.2 C7.2 C8.2 C9.2 C10.2 C11.2 C12.2 C13.2 C15.2 C16.2 C26.2 C27.2 C28.2 C29.2 C30.2 C31.2 C32.2 C33.2 C36.2 CM1.3 CN1.4 CN1.7 CN1.10 CN1.13 CN1.16 CN1.19 CN1.22 CN1.25 CN1.30 CN2.4 CN2.7 CN2.10 CN2.13 CN2.16 CN2.19 CN2.22 CN3.1 CN3.10 CP1.2 CP2.2 CP3.1 CP4.1 J1.5 J2.4 R4.2 R10.1 R12.1 R14.1 R16.1 R66.2 R67.2 R71.2 R72.2 TV2.3 TV2.8 TV3.3 TV3.8 TV4.3 TV4.8 U1.3 U2.4 U4.2 | length 22979.8
  TopLayer w6: CN2.7@1498.03,2414.85 1553.11,2414.85 ; 1635.33,2420.33 TV4.3@1667.73,2420.33 ; TV4.8@1692.14,2420.33 1729.59,2420.33 ; v2(1725,2475) 1733.64,2475 1831.89,2573.25 1886.75,2573.25 1930,2530 2021.77,2530 2065.02,2573.25 2426.75,2573.25 2470,2530 2574.9,2530 2618.15,2573.25 2726.75,2573.25 2770,2530 2899.9,2530 2943.15,2573.25 3030.25,2573.25 3073.5,2530 3199.9,2530 3243.15,2573.25 3326.85,2573.25 3343.92,2556.18 3343.92,2343.92 3286.81,2286.81 3286.81,791.81 3271.38,776.38 CN1.19@3271.38,745 ; v2@1725,2530 v2(1725,2531.36) 1797.39,2603.75 1899.48,2603.75 1933.23,2570 2018.63,2570 2052.38,2603.75 2446.25,2603.75 2480,2570 2571.77,2570 2605.52,2603.75 2744.25,2603.75 2778,2570 2896.77,2570 2930.52,2603.75 3044.25,2603.75 3078,2570 3196.77,2570 3230.52,2603.75 3339.48,2603.75 3374.42,2568.81 3374.42,2329.42 3345.86,2300.86 3345.86,795.86 3330.43,780.43 CN1.16@3330.43,738.19 ; v2(1725,2590) 1730,2590 1774.25,2634.25 1912.11,2634.25 1936.36,2610 2015.5,2610 2039.75,2634.25 2461.25,2634.25 2485.5,2610 2568.64,2610 2592.89,2634.25 2756.88,2634.25 2781.13,2610 2893.64,2610 2917.89,2634.25 3056.88,2634.25 3081.13,2610 3193.64,2610 3217.89,2634.25 3352.11,2634.25 3404.92,2581.45 3404.92,795.43 3389.49,780 CN1.13@3389.49,738.19 ; v2(1725,2650) 1739.75,2664.75 3402.87,2664.75 3463.97,2603.65 3463.97,793.97 3448.54,778.54 CN1.10@3448.54,738.19 ; 3212.32,690.66 CN1.22@3212.32,738.19 ; C10.2@3562.05,960.12 3566.65,955.51 3566.65,795.99
  TopLayer w10: 3054.84,697.77 CN1.30@3054.84,738.19 ; 3153.27,681.6 3153.27,787.01 ; CN1.22@3212.32,735 v1@3212.32,798.06 ; 3507.6,685.93 CN1.7@3507.6,738.19 ; CN1.4@3566.65,738.19 3566.65,795.99
  TopLayer w12: CN2.4@1498.03,2355.79 2874.21,2355.79 3015,2215 3015,940 3054.84,900.16 CN1.30@3054.84,738.19 ; v2(1725,2705) 1731.75,2698.25 3416.75,2698.25 3507.6,2607.4 CN1.7@3507.6,738.19 ; v2@2199.24,3353.23 U1.3@2222.49,3353.23 2222.49,3329.66 ; CN1.19@3271.38,738.19 CN1.19@3271.38,745
  TopLayer w15: CN3.10@1424.13,147.64 1424.13,207.53 ; CN3.1@1601.3,147.64 1613.66,160 1631.67,160
  TopLayer w20: C29.2@848.66,3431.46 848.66,3464.53 v3(850.71,3466.57) ; C30.2@851.77,3629.17 851.77,3596.34 v3(853.82,3594.29) ; C31.2@851.77,3949.17 851.77,3916.34 v3(853.82,3914.29) ; v3(1088.82,3657.22) 1092.44,3653.6 U4.2@1140.26,3653.6 ; J2.4@1410,4135 1420.03,4124.97 C26.2@1420.03,3972.61
  TopLayer w30: 2601.26,3340 2798.74,3340 ; v1@2631.38,4170.12 B4.2@2709.86,4170.12 2709.86,4083.88 ; v2@2817.02,3600.76 CM1.3@2883.13,3600.76 2883.13,3545.6 2881.27,3543.74
  other v1: 256.67,75 1220,103.74 1830,103.74 2325,118.74 2051.67,165 1670,178.74 1881.67,190 625,193.74 105,203.74 1345,223.74 1406.67,230 3736.67,230 786.67,250 1941.67,260 1796.67,300 2570,328.74 765,353.74 2995,363.74 3585,363.74 3301.67,400 1175,403.74 1796.67,410 2046.67,580 1085,603.74 3040,613.74 1290,618.74 560,643.74 3200,653.74 3291.67,655 3391.67,655 3490,663.74 1406.67,665 1285,693.74 2366.67,710 1141.67,745 1820,773.74 2251.67,775 3207.67,805 3275,807.74 3151.67,810 3331.67,810 3391.67,810 3450.67,810 2450,828.74 570,833.74 3521.67,865 2645,903.74 995,913.74 1461.67,925 1055,933.74 705,938.74 3455,938.74 3195,958.74 2720,1008.74 3510,1012.74 3271.67,1015 2975,1023.74 3120,1048.74 766.67,1100 3510,1133.74 3006.67,1160 3333.67,1165 3710,1205 3390,1289.74 3455,1357.74 1685,1393.74 1026.67,1395 1421.67,1410 3547.67,1460 3751.67,1470 3100,1533.74 1696.67,1535 3270,1542.74 820,1583.74 3393.67,1655 3535,1669.74 1405,1673.74 1681.67,1680 3330,1729.74 1030,1793.74 1190,1798.74 3076.67,1945 1685,1978.74 3731.67,2010 1401.67,2015 3330,2170.74 3390,2212.74 3270,2214.74 2785,2233.74 2296.67,2235 3451.67,2235 2535,2243.74 1691.67,2270 811.67,2280 2390,2298.74 2525,2318.74 2990,2328.74 1850,2348.74 1586.67,2355 2115,2363.74 1415,2443.74 3007.67,2470 3261.67,2470 2685,2482.74 2188.67,2495 1406.67,2530 1041.67,2535 1411.67,2605 3750,2678.74 1416.67,2690 3531.67,2690 2215,2723.74 2960,2726.74 810,2728.74 1700,2853.74 1860,2858.74 2680,2983.74 3320,2988.74 3081.67,3050 3216.67,3065 1070,3093.74 2700,3123.74 1701.67,3130 1460,3143.74 3000,3168.74 781.67,3190 3131.67,3210 2741.67,3245 2636.67,3250 3010,3253.74 3740,3258.74 2701.67,3270 3271.67,3270 3516.67,3295 3371.67,3330 1625,3368.74 1275,3393.74 1455,3428.74 1801.67,3445 3520,3453.74 3725,3453.74 2551.67,3510 2696.67,3510 1265,3548.74 2538.07,3620.35 1751.67,3635 2066.67,3670 2538.07,3675.35 2275,3693.74 2346.67,3720 1035,3728.74 2186.67,3750 1915,3793.74 2590,3843.74 1330,3863.74 1055,3943.74 2421.67,3995 2070,4088.74 2711.67,4095 2645,4103.74 2635,4173.74 971.67,4250 2470,4278.74 1726.67,4290 1201.67,4300
  other v2: 2146.23,3250.21 2326.23,3255.21 2126.23,3280.21 2161.23,3280.21 2196.23,3280.21 2291.23,3290.21 2126.23,3315.21 2161.23,3315.21 2196.23,3315.21 2126.23,3350.21 2161.23,3350.21 2196.23,3350.21 2755.08,3573.86 2940.08,3573.86 2755.08,3598.86 2820.08,3598.86 2755.08,3623.86 2820.08,3623.86
  other v3: 2291.23,3260.21 2391.23,3260.21 2321.23,3290.21 2286.23,3320.21 2316.23,3320.21 2340,3450 2400,3450 950,3460 1025,3460 2820.08,3573.86 2940.08,3598.86 2940.08,3623.86 2648.15,3644.21 2648.15,3669.21 2648.15,3694.21 2538.07,3730.35 1375,3970
ICPDA: J2.2 U4.1 | length 475.6
  TopLayer w15: U4.1@1140.26,3703.6 1166.4,3703.6 1185,3722.2 1185,4005 1210,4030 J2.2@1210,4135
ICPDK: J2.3 U4.15 | length 603.6
  TopLayer w15: J2.3@1310,4135 1310,4040 1245,3975 1245,3687.2 1278.6,3653.6 U4.15@1359.95,3653.6
INT: CN3.5 R19.1 | length 318.2
  TopLayer w8: R19.1@1418.87,422.91 1522.56,319.23 CN3.5@1522.56,147.64
KEY1: C29.1 R37.2 R57.1 U4.5 | length 577.8
  TopLayer w15: R57.1@848.21,3341.57 848.21,3351.79 792.93,3407.07 R37.2@792.93,3530.76 828.7,3495 967.8,3495 976.4,3503.6 U4.5@1140.26,3503.6
KEY2: C30.1 R38.2 R58.1 U4.4 | length 601.8
  TopLayer w15: R38.2@796.04,3718.48 796.04,3588.96 820,3565 1005,3565 1016.4,3553.6 U4.4@1140.26,3553.6 ; R38.2@796.77,3718.48 796.77,3741.77 851.32,3796.32 R58.1@851.32,3809.29
KEY3: C31.1 R39.2 R59.1 U4.3 | length 847.4
  TopLayer w15: R59.1@851.32,4129.29 851.32,4106.79 796.04,4051.51 796.04,3883.96 815,3865 910,3865 955,3820 955,3617.2 968.6,3603.6 U4.3@1140.26,3603.6
LCM_3.3V: C8.1 C9.1 C10.1 C33.1 CN1.2 CN1.3 FB1.2 R68.2 | length 190.4
  TopLayer w10: CN1.3@3586.34,738.19 3586.34,786.34 3595,795 ; CN1.2@3606.02,738.19 3606.02,793.98 ; C33.1@3617.99,1169 R68.2@3692.24,1169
